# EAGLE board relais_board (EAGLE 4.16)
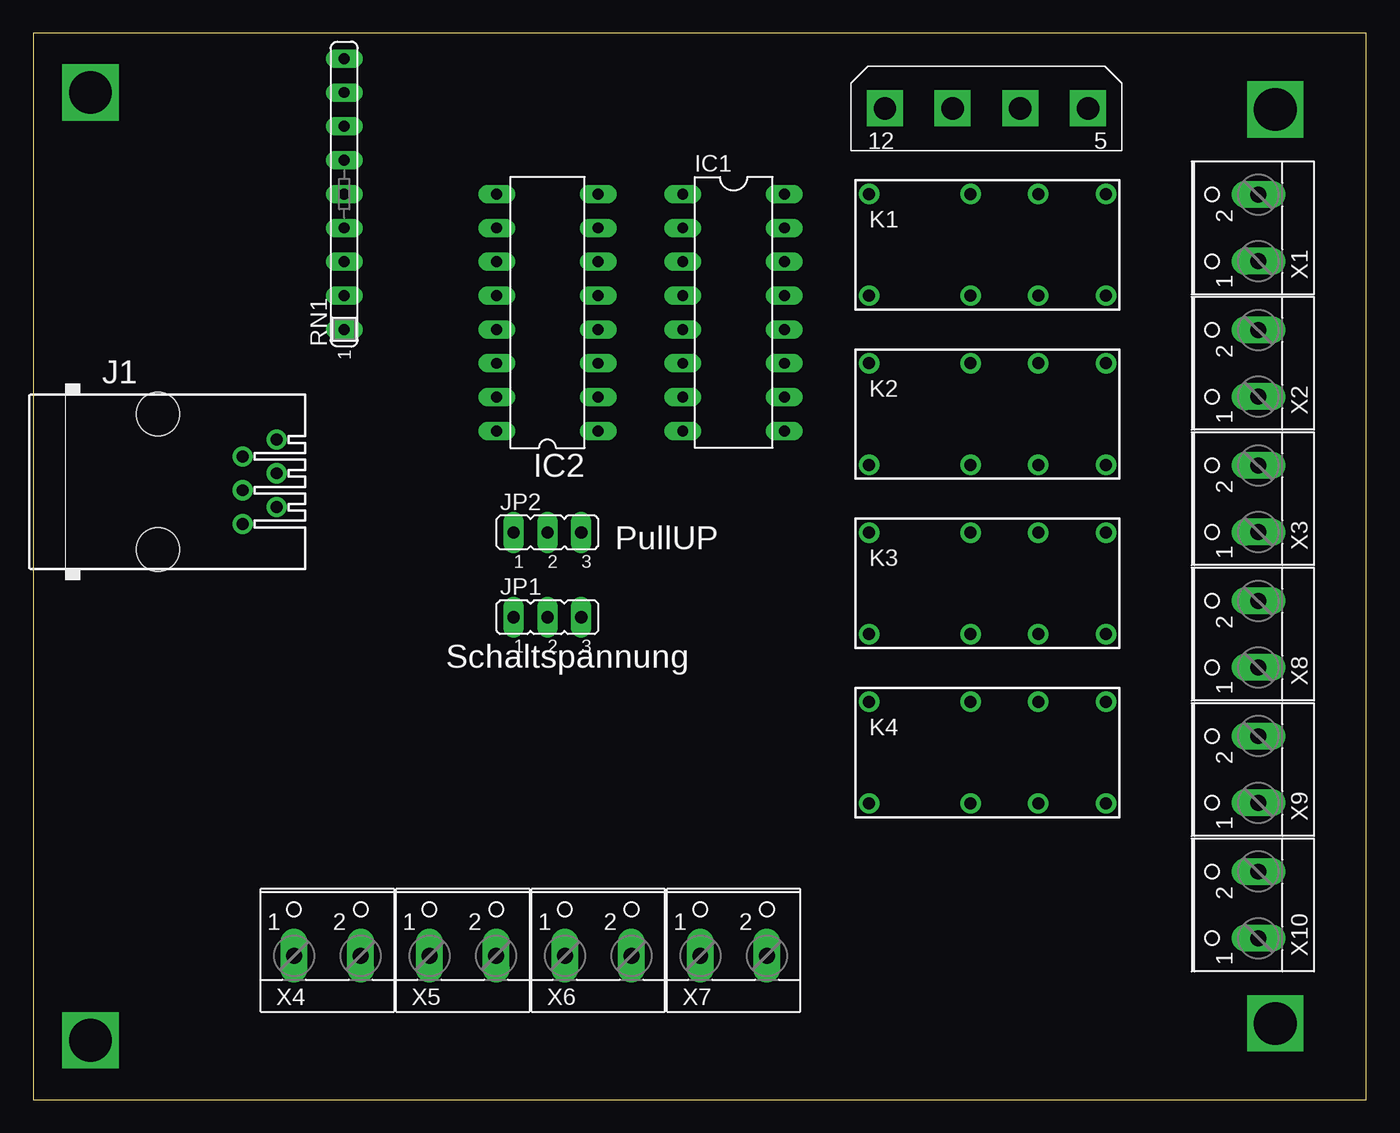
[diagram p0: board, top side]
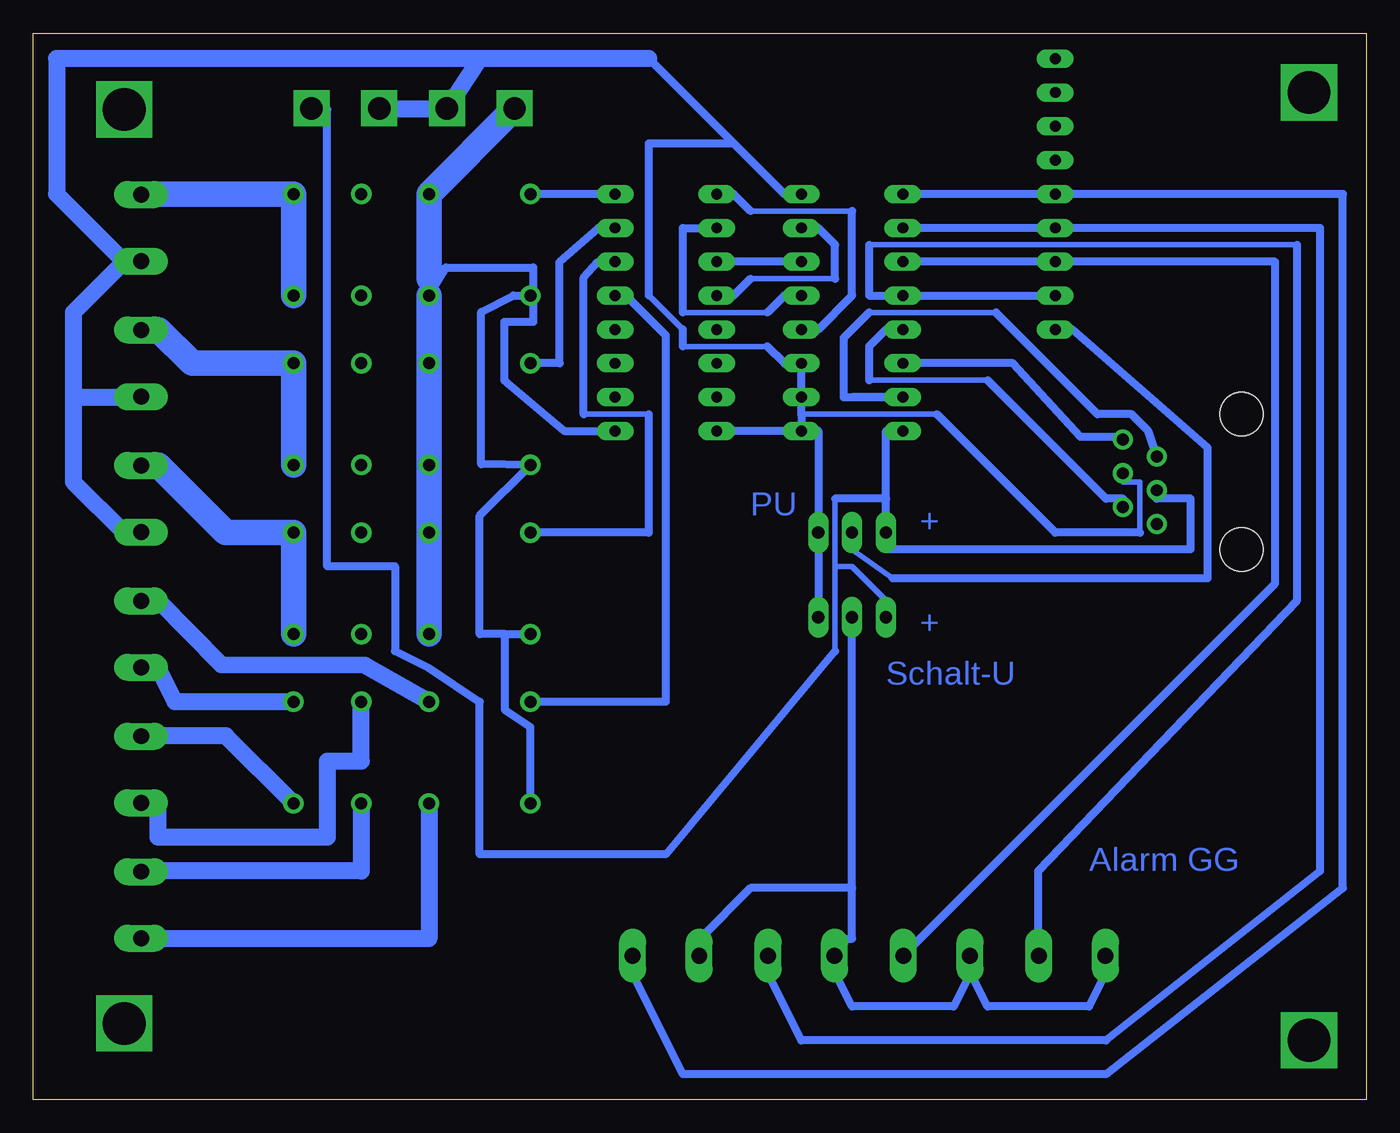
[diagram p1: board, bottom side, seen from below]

Size 100 x 80 mm. Coordinates in mm from the lower left corner, seen from the top.
Outline: 0,0 100,0 100,80 0,80 0,0
Copper layers (1*16): Top 0.035mm / dielectric 1.5mm / Bottom 0.035mm
Design rules "default": minimum track width 10mil, minimum drill 24mil, track to track 8mil, track to pad 8mil, pad to pad 8mil, via to via 8mil, smd to smd 8mil, copper to edge 40mil, drill to drill 8mil, minimum pad ring 10mil, minimum via ring 8mil, stop-mask expansion 4mil, vias tented up to drill 0mil, thermal gap 10mil

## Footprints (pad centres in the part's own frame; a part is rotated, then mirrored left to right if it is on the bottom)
PSG5 = drill 1.676 square: 0V -2.62,0.08; 0V-B 2.46,0.08; 5V 7.54,0.08; 12V -7.7,0.08
DIL16 = drill 0.813 long: 1 -8.89,-3.81; 2 -6.35,-3.81; 3 -3.81,-3.81; 4 -1.27,-3.81; 5 1.27,-3.81; 6 3.81,-3.81; 7 6.35,-3.81; 8 8.89,-3.81; 9 8.89,3.81; 10 6.35,3.81; 11 3.81,3.81; 12 1.27,3.81; 13 -1.27,3.81; 14 -3.81,3.81; 15 -6.35,3.81; 16 -8.89,3.81
520250-3 = drill 0.889 round: 1 -3.175,8.89; 2 -1.905,6.35; 3 -0.635,8.89; 4 0.635,6.35; 5 1.905,8.89; 6 3.175,6.35 | hole 3.251: -5.08,0; 5.08,0
JP2 = drill 0.914 long: 1 -2.54,0; 2 0,0; 3 2.54,0
DS2Y = drill 0.9 round: 1 -8.89,-3.81; 4 -1.27,-3.81; 6 3.81,-3.81; 8 8.89,-3.81; 9 8.89,3.81; 11 3.81,3.81; 13 -1.27,3.81; 16 -8.89,3.81
SIL9 = drill 0.813 long: 1 -10.16,0; 2 -7.62,0; 3 -5.08,0; 4 -2.54,0; 5 0,0; 6 2.54,0; 7 5.08,0; 8 7.62,0; 9 10.16,0
W237-102 = drill 1.194 long: 1 -2.5,-1.27; 2 2.5,-1.27

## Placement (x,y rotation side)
1  [PSG5]  71.59,74.29 0 top
IC1  ULN2003AN  [DIL16]  52.54,59.05 270 top
IC2  PCF8574P  [DIL16]  38.57,59.05 90 top
J1  [520250-3]  9.36,46.35 270 top
JP1  [JP2]  38.57,36.19 0 top
JP2  [JP2]  38.57,42.54 0 top
K1  DS2Y-S-DC12V  [DS2Y]  71.59,64.13 0 top
K2  DS2Y-S-DC12V  [DS2Y]  71.59,51.43 0 top
K3  DS2Y-S-DC12V  [DS2Y]  71.59,38.73 0 top
K4  DS2Y-S-DC12V  [DS2Y]  71.59,26.03 0 top
RN1  [SIL9]  23.33,67.94 90 top
X1  [W237-102]  90.64,65.4 90 top
X2  [W237-102]  90.64,55.24 90 top
X3  [W237-102]  90.64,45.08 90 top
X4  [W237-102]  22.06,12.06 0 top
X5  [W237-102]  32.22,12.06 0 top
X6  [W237-102]  42.38,12.06 0 top
X7  [W237-102]  52.54,12.06 0 top
X8  [W237-102]  90.64,34.92 90 top
X9  [W237-102]  90.64,24.76 90 top
X10  [W237-102]  90.64,14.6 90 top

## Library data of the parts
1 = PSG5
IC1 = uln-udn
IC2 = micro-philips
J1 = con-amp
JP1 JP2 = jumper
K1-K4 = relay
RN1 = resistor-sil
X1-X10 = con-wago-500

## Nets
+5V: 1.5V IC2.16 J1.4 JP1.1 JP2.1
+12V: 1.12V IC1.9 K1.4 K1.13 K2.4 K2.13 K3.4 K3.13
GND: 1.0V 1.0V-B IC1.8 IC2.1 IC2.2 IC2.3 IC2.8 J1.3 JP1.3 JP2.3 X1.1 X2.1 X3.1
N$1: IC2.14 J1.1
N$2: IC2.15 J1.2
N$3: IC1.16 K1.16
N$4: IC1.1 IC2.4
N$5: IC1.2 IC2.5
N$6: IC1.3 IC2.6
N$7: IC1.4 IC2.7
N$8: IC2.13 J1.5
N$9: K1.8 K1.9 X1.2
N$10: K2.8 K2.9 X2.2
N$11: K3.8 K3.9 X3.2
N$12: K1.1 K2.1 K3.1 K4.1
N$13: IC1.14 K3.16
N$14: IC1.15 K2.16
N$15: JP1.2 X4.1 X5.1 X6.1 X7.1
N$20: IC1.13 K4.16
N$21: K4.6 X10.2
N$22: K4.4 X10.1
N$23: K4.8 X9.2
N$24: K4.11 X9.1
N$25: K4.13 X8.2
N$26: K4.9 X8.1
N$27: IC2.9 RN1.5 X7.2
N$28: IC2.10 RN1.4 X6.2
N$29: IC2.11 RN1.3 X5.2
N$30: IC2.12 RN1.2 X4.2
N$31: JP2.2 RN1.1

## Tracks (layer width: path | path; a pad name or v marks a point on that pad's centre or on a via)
+5V
  Bottom 0.254: 36.03,37.46 JP1.1
  Bottom 0.406: 36.03,37.46 38.57,40 39.84,40 | 39.84,45.08 39.84,40 | 39.84,40 39.84,33.65
  Bottom 0.61: 36.03,45.08 36.03,50.16 IC2.16 | 36.03,45.08 JP2.1 36.03,41.27 13.17,41.27 13.17,45.08 15.71,45.08 J1.4 | 36.03,45.08 39.84,45.08 | 39.84,33.65 52.54,18.41 66.51,18.41 66.51,29.84 70.32,32.38 72.86,33.65 72.86,40 77.94,40 77.94,74.29 1.5V
+12V
  Bottom 0.254: 1.12V 63.97,74.29
  Bottom 0.61: 69.05,62.44 62.5,62.43 62.5,58.34 64.68,58.34 64.68,53.97 60.16,50.16 IC1.9 | K1.4 69.05,62.44 | 69.05,62.44 70.32,61.59
  Bottom 1.93: K3.4 K3.13 K2.4 K2.13 K1.4 | 70.32,61.59 K1.13 63.97,74.29
GND
  Bottom 0.254: 93.18,42.54 X3.1 | 93.18,52.7 X2.1 | 43.65,67.94 IC2.8 | 72.86,74.29 1.0V-B | 1.0V 69.05,74.29 | 93.18,62.86 X1.1 | IC2.3 43.65,55.24
  Bottom 0.406: 16.98,42.54 16.98,46.35 18.25,46.35 J1.3 | 32.22,51.43 42.38,51.43 | 44.92,56.51 51.27,56.51 | 51.27,57.78 53.81,60.32
  Bottom 0.61: JP1.3 JP2.3 41.11,50.16 IC2.1 | IC2.1 42.38,51.43 IC2.2 IC2.3 | IC2.1 IC1.8 | 16.98,42.54 23.33,42.54 32.22,51.43 | 47.46,71.75 53.81,78.1 | 47.46,71.75 43.65,67.94 | 43.65,55.24 44.92,56.51 | 51.27,56.51 51.27,57.78 | 53.81,60.32 53.81,71.75 47.46,71.75
  Bottom 1.27: 93.18,42.54 96.99,46.35 96.99,52.7 | 96.99,52.7 93.18,52.7 | 96.99,52.7 96.99,59.05 93.18,62.86 98.26,67.94 98.26,78.1 66.51,78.1 | 53.81,78.1 66.51,78.1 | 66.51,78.1 1.0V | 69.05,74.29 72.86,74.29
N$1
  Bottom 0.61: IC2.14 26.5,55.24 21.42,49.72 18.25,49.72 J1.1
N$2
  Bottom 0.406: 27.77,59.05 37.3,59.05
  Bottom 0.61: 27.77,59.05 20.15,51.43 17.61,51.43 16.34,50.16 J1.2 | 38.57,52.7 IC2.15 39.2,52.7 39.2,57.15 37.3,59.05
N$3
  Bottom 0.61: IC1.16 K1.16
N$4
  Bottom 0.254: IC2.4 41.11,57.78 | 47.46,67.94 IC1.1
  Bottom 0.406: 38.57,66.67 46.19,66.67
  Bottom 0.61: 41.11,57.78 38.57,60.32 38.57,66.67 | 46.19,66.67 47.46,67.94
N$5
  Bottom 0.254: IC2.5 43.65,60.32
  Bottom 0.406: 44.92,59.05 51.27,59.05
  Bottom 0.61: 43.65,60.32 44.92,59.05 | 51.27,59.05 51.27,65.4 IC1.2
N$6
  Bottom 0.61: IC2.6 IC1.3
N$7
  Bottom 0.254: 41.11,65.4 IC2.7 | 47.46,60.32 IC1.4
  Bottom 0.406: 39.84,61.59 46.19,61.59
  Bottom 0.61: 41.11,65.4 39.84,64.13 39.84,61.59 | 46.19,61.59 47.46,60.32
N$8
  Bottom 0.254: J1.5 18.25,45.08
  Bottom 0.406: 28.41,53.97 37.3,53.97
  Bottom 0.61: 37.3,53.97 37.3,56.51 36.03,57.78 IC2.13 | 28.41,53.97 19.52,45.08 18.25,45.08
N$9
  Bottom 0.254: 90.64,67.94 X1.2
  Bottom 1.93: K1.8 K1.9 90.64,67.94
N$10
  Bottom 0.254: 90.64,57.78 X2.2
  Bottom 1.93: K2.8 K2.9 88.1,55.24 90.64,57.78
N$11
  Bottom 0.254: 90.64,47.62 X3.2
  Bottom 1.93: K3.8 K3.9 85.56,42.54 90.64,47.62
N$12
  Bottom 0.61: K4.1 62.7,27.93 64.61,29.2 64.61,34.92 | 64.61,34.92 K3.1 | 64.61,34.92 66.51,34.92 66.51,43.81 K2.1 66.4,47.66 66.4,59.1 63.97,60.32 K1.1
N$13
  Bottom 0.406: 58.71,51.43 53.81,51.43
  Bottom 0.61: 58.71,51.43 58.71,61.68 57.62,62.86 IC1.14 | 53.81,51.43 53.81,42.54 K3.16
N$14
  Bottom 0.61: K2.16 60.52,55.24 60.52,62.86 57.62,65.4 IC1.15
N$15
  Bottom 0.254: 50,12.06 X7.1
  Bottom 0.61: 29.68,9.52 28.41,6.98 20.79,6.98 19.52,9.52 X4.1 | 38.57,15.87 38.57,12.06 39.84,12.06 X6.1 39.84,9.52 38.57,6.98 30.95,6.98 29.68,9.52 | 38.57,15.87 JP1.2 | 29.68,9.52 X5.1 | 50,12.06 46.19,15.87 38.57,15.87
N$16  (via drill 3.2)
  other vias: 93.18,5.71
N$17  (via drill 3.2)
  other vias: 93.18,74.29
N$18  (via drill 3.2)
  other vias: 4.28,75.56
N$19  (via drill 3.2)
  other vias: 4.28,4.44
N$20
  Bottom 0.254: 55.08,59.88 IC1.13
  Bottom 0.61: 55.08,59.88 52.54,57.34 52.54,29.84 K4.16
N$21
  Bottom 0.254: 90.64,17.14 X10.2
  Bottom 1.27: K4.6 75.4,17.14 90.64,17.14
N$22
  Bottom 0.254: 90.64,12.06 X10.1
  Bottom 1.27: K4.4 70.32,12.06 90.64,12.06
N$23
  Bottom 0.254: 90.64,27.3 X9.2
  Bottom 1.27: K4.8 85.56,27.3 90.64,27.3
N$24
  Bottom 0.254: 90.64,22.22 X9.1
  Bottom 1.27: K4.11 75.4,25.39 77.94,25.39 77.94,19.68 90.64,19.68 90.64,22.22
N$25
  Bottom 0.254: 90.64,37.46 X8.2
  Bottom 1.27: K4.13 75.13,32.57 85.87,32.62 90.64,37.46
N$26
  Bottom 0.254: 90.64,32.38 X8.1
  Bottom 1.27: K4.9 89.37,29.84 90.64,32.38
N$27
  Bottom 0.61: IC2.9 RN1.5 1.74,67.94 1.74,15.87 19.52,1.9 51.27,1.9 55.08,9.52 X7.2
N$28
  Bottom 0.61: IC2.10 RN1.4 3.46,65.4 3.46,17.14 19.52,4.44 42.38,4.44 44.92,9.52 X6.2
N$29
  Bottom 0.254: X5.2 34.76,12.06
  Bottom 0.61: IC2.11 RN1.3 6.82,62.86 6.82,38.73 34.76,10.79 X5.2
N$30
  Bottom 0.406: 5.17,64.13 37.3,64.13
  Bottom 0.61: RN1.2 IC2.12 37.3,60.32 37.3,64.13 | 5.17,64.13 5.17,37.46 24.6,17.14 24.6,12.06 X4.2
N$31
  Bottom 0.406: 35.52,39.11 38.57,41.27
  Bottom 0.61: 35.52,39.11 11.9,39.11 11.9,48.89 22.06,57.78 RN1.1 | 38.57,41.27 JP2.2
N$32  (via drill 1)
  other vias: 9.36,51.43
N$33  (via drill 1)
  other vias: 9.36,41.27

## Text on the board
Bottom: PU | + | + | Schalt-U | Alarm GG
tNames: PullUP | Schaltspannung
